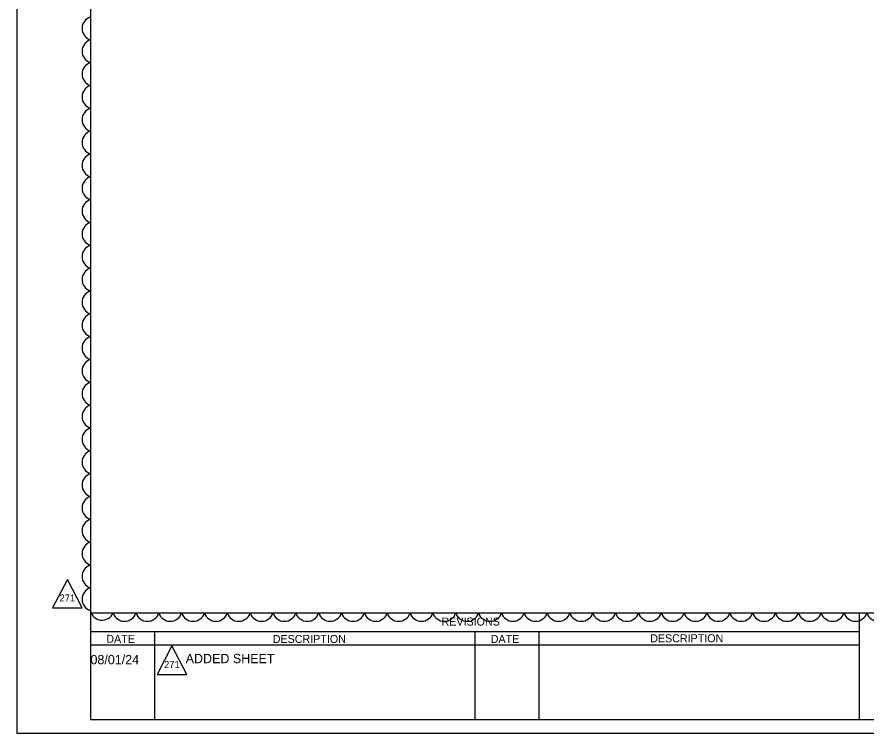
# Model space of a CAD drawing. Extents: x -816.9 to -790.1, y -2199.5 to -2184.5.
# Drawn here: x -811.34 to -804.97, y -2199.5 to -2194.13 of the extents above; entities that cross this region are included whole.
import ezdxf

# ---------------------------------------------------------------- set-up
doc = ezdxf.new("R2010")
doc.units = 0
for name, color, linetype in [('AdhocPoint_dp', 7, 'Continuous'), ('Cloud_dp', 7, 'Continuous'), ('PlotBorder_dp', 7, 'Continuous'), ('SheetBorder_dp', 7, 'Continuous'), ('SheetLines_dp', 7, 'Continuous'), ('TextLabel', 7, 'Continuous'), ('TextMisc', 7, 'Continuous')]:
    doc.layers.add(name, color=color, linetype=linetype)

msp = doc.modelspace()

# ---------------------------------------------------------------- linework, layer by layer
at = {"layer": 'AdhocPoint_dp'}
msp.add_line((-811.3358, -2199.5006), (-811.3358, -2199.5006), dxfattribs=at)
at = {"layer": 'Cloud_dp'}
for points in [[(-810.9581, -2198.3492), (-811.069, -2198.5629), (-810.8472, -2198.5629)], [(-810.1749, -2198.8478), (-810.2858, -2199.0614), (-810.064, -2199.0614)]]:
    msp.add_lwpolyline(points, close=True, dxfattribs=at)
for centre, radius, start, end in [((-810.7588, -2194.2199), 0.0897, 107.5, 252.5), ((-810.7588, -2194.391), 0.0897, 107.5, 252.5), ((-810.7588, -2194.5621), 0.0897, 107.5, 252.5), ((-810.7588, -2194.7332), 0.0897, 107.5, 252.5), ((-810.7588, -2194.9044), 0.0897, 107.5, 252.5), ((-810.7588, -2195.0755), 0.0897, 107.5, 252.5), ((-810.7588, -2195.2466), 0.0897, 107.5, 252.5), ((-810.7588, -2195.4177), 0.0897, 107.5, 252.5), ((-810.7588, -2195.5889), 0.0897, 107.5, 252.5), ((-810.7588, -2195.76), 0.0897, 107.5, 252.5), ((-810.7588, -2195.9311), 0.0897, 107.5, 252.5), ((-810.7588, -2196.1022), 0.0897, 107.5, 252.5), ((-810.7588, -2196.2733), 0.0897, 107.5, 252.5), ((-810.7588, -2196.4445), 0.0897, 107.5, 252.5), ((-810.7588, -2196.6156), 0.0897, 107.5, 252.5), ((-810.7588, -2196.7867), 0.0897, 107.5, 252.5), ((-810.7588, -2196.9578), 0.0897, 107.5, 252.5), ((-810.7588, -2197.129), 0.0897, 107.5, 252.5), ((-810.7588, -2197.3001), 0.0897, 107.5, 252.5), ((-810.7588, -2197.4712), 0.0897, 107.5, 252.5), ((-810.7588, -2197.6423), 0.0897, 107.5, 252.5), ((-810.7588, -2197.8134), 0.0897, 107.5, 252.5), ((-810.7588, -2197.9846), 0.0897, 107.5, 252.5), ((-810.7588, -2198.1557), 0.0897, 107.5, 252.5), ((-810.7588, -2198.3268), 0.0897, 107.5, 252.5), ((-810.7588, -2198.4979), 0.0897, 107.5, 252.5), ((-810.698, -2198.5653), 0.0896, 191.74536, 336.74536), ((-810.5301, -2198.5737), 0.0897, 197.5, 342.5), ((-810.359, -2198.5737), 0.0897, 197.5, 342.5), ((-810.1879, -2198.5737), 0.0897, 197.5, 342.5), ((-810.0167, -2198.5737), 0.0897, 197.5, 342.5), ((-809.8456, -2198.5737), 0.0897, 197.5, 342.5), ((-809.6745, -2198.5737), 0.0897, 197.5, 342.5), ((-809.5034, -2198.5737), 0.0897, 197.5, 342.5), ((-809.3323, -2198.5737), 0.0897, 197.5, 342.5), ((-809.1611, -2198.5737), 0.0897, 197.5, 342.5), ((-808.99, -2198.5737), 0.0897, 197.5, 342.5), ((-808.8189, -2198.5737), 0.0897, 197.5, 342.5), ((-808.6478, -2198.5737), 0.0897, 197.5, 342.5), ((-808.4766, -2198.5737), 0.0897, 197.5, 342.5), ((-808.3055, -2198.5737), 0.0897, 197.5, 342.5), ((-808.1344, -2198.5737), 0.0897, 197.5, 342.5), ((-807.9633, -2198.5737), 0.0897, 197.5, 342.5), ((-807.7921, -2198.5737), 0.0897, 197.5, 342.5), ((-807.621, -2198.5737), 0.0897, 197.5, 342.5), ((-807.4499, -2198.5737), 0.0897, 197.5, 342.5), ((-807.2788, -2198.5737), 0.0897, 197.5, 342.5), ((-807.1077, -2198.5737), 0.0897, 197.5, 342.5), ((-806.9365, -2198.5737), 0.0897, 197.5, 342.5), ((-806.7654, -2198.5737), 0.0897, 197.5, 342.5), ((-806.5943, -2198.5737), 0.0897, 197.5, 342.5), ((-806.4232, -2198.5737), 0.0897, 197.5, 342.5), ((-806.252, -2198.5737), 0.0897, 197.5, 342.5), ((-806.0809, -2198.5737), 0.0897, 197.5, 342.5), ((-805.9098, -2198.5737), 0.0897, 197.5, 342.5), ((-805.7387, -2198.5737), 0.0897, 197.5, 342.5), ((-805.5676, -2198.5737), 0.0897, 197.5, 342.5), ((-805.3964, -2198.5737), 0.0897, 197.5, 342.5), ((-805.2253, -2198.5737), 0.0897, 197.5, 342.5), ((-805.0542, -2198.5737), 0.0897, 197.5, 342.5), ((-804.8831, -2198.5737), 0.0897, 197.5, 342.5)]:
    msp.add_arc(centre, radius, start, end, dxfattribs=at)
at = {"layer": 'PlotBorder_dp'}
msp.add_lwpolyline([(-811.3358, -2199.5006), (-794.8358, -2199.5006), (-794.8358, -2188.9006), (-811.3358, -2188.9006)], close=True, dxfattribs=at)
at = {"layer": 'SheetBorder_dp'}
for p, q in [((-810.7858, -2189.0006), (-810.7858, -2199.4006)), ((-810.7858, -2198.6006), (-795.3858, -2198.6006)), ((-810.7858, -2199.4006), (-795.3858, -2199.4006))]:
    msp.add_line(p, q, dxfattribs=at)
at = {"layer": 'SheetLines_dp'}
for p, q in [((-805.0258, -2198.6006), (-805.0258, -2199.4006)), ((-810.7858, -2198.7406), (-805.0258, -2198.7406)), ((-810.3058, -2198.7406), (-810.3058, -2199.4006)), ((-807.9058, -2198.7406), (-807.9058, -2199.4006)), ((-807.4258, -2198.7406), (-807.4258, -2199.4006)), ((-810.7858, -2198.8406), (-805.0258, -2198.8406))]:
    msp.add_line(p, q, dxfattribs=at)

# ---------------------------------------------------------------- texts
at = {"layer": 'Cloud_dp'}
for p in [(-811.0171, -2198.5147), (-810.2339, -2199.0133)]:
    msp.add_text('271', height=0.0525, rotation=360, dxfattribs=at).set_placement(p)
at = {"layer": 'TextLabel'}
for s, p in [('08/01/24', (-810.7853, -2198.9855)), ('ADDED SHEET', (-810.0721, -2198.9774))]:
    msp.add_text(s, height=0.07, rotation=0, dxfattribs=at).set_placement(p)
at = {"layer": 'TextMisc'}
msp.add_text('REVISIONS', height=0.06, dxfattribs=at).set_placement((-808.1553, -2198.6955))
for s, rotation, p in [('DATE', 359.86925, (-810.6668, -2198.8247)), ('DESCRIPTION', 0.04975, (-809.4198, -2198.8259)), ('DATE', 359.86925, (-807.7868, -2198.8253)), ('DESCRIPTION', 0.04975, (-806.5922, -2198.8209))]:
    msp.add_text(s, height=0.06, rotation=rotation, dxfattribs=at).set_placement(p)

doc.saveas('drawing.dxf')
